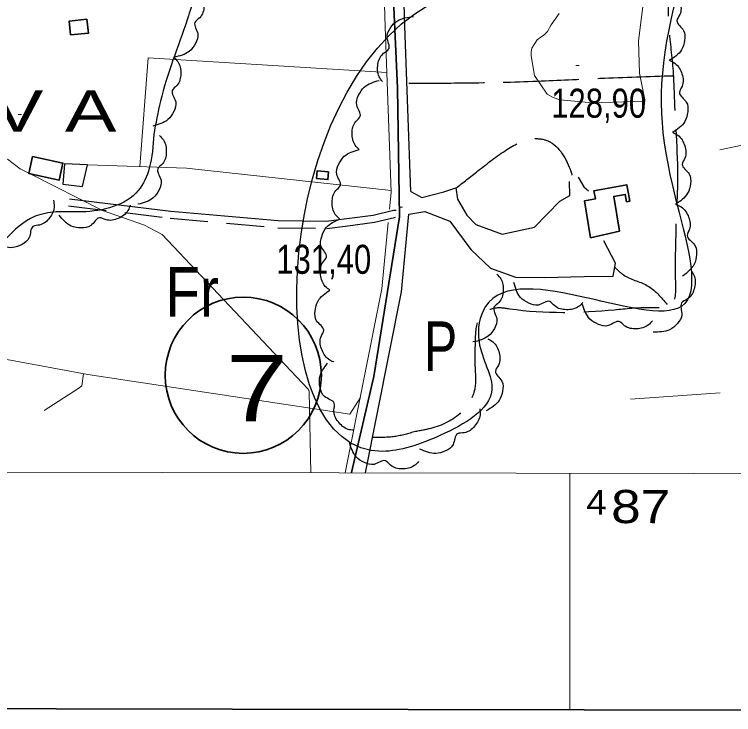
# Model space of a CAD drawing. Extents: x 483847 to 488453, y 4383581 to 4386795.
# Drawn here: x 486832.5 to 487049.4, y 4384057.5 to 4384268.7 of the extents above; entities that cross this region are included whole.
import ezdxf
from ezdxf.enums import TextEntityAlignment as Align

# ---------------------------------------------------------------- set-up
doc = ezdxf.new("R2010")
doc.units = 0
doc.header["$LTSCALE"] = 3.8
for name, pattern in [('DOTTED', [1.5, 0.3, -1.2]), ('LONG_DASHED', [7.5, 6, -1.5]), ('MEDIUM_DASHED', [4.5, 3, -1.5])]:
    doc.linetypes.add(name, pattern=pattern)
for name, color, linetype, lineweight in [('1', 7, 'Continuous', 13), ('13', 7, 'Continuous', 25), ('2', 7, 'DOTTED', 13), ('21', 7, 'Continuous', 25), ('25', 7, 'LONG_DASHED', 25), ('27', 7, 'Continuous', 25), ('38', 7, 'Continuous', 25), ('47', 7, 'Continuous', 35), ('51', 7, 'Continuous', 13), ('6', 7, 'Continuous', 35), ('7', 7, 'Continuous', 13), ('9', 7, 'Continuous', 13)]:
    doc.layers.add(name, color=color, linetype=linetype, lineweight=lineweight)
doc.layers.add('31', color=7, linetype='Continuous')
doc.layers.add('5', color=7, linetype='Continuous')

msp = doc.modelspace()

# ---------------------------------------------------------------- linework, layer by layer
at = {"layer": '1'}
msp.add_line((487000, 4384130.29), (487000, 4384058.94), dxfattribs=at)
at = {"layer": '1', "lineweight": 35}
msp.add_lwpolyline([(484035.03, 4386519.58), (487752.53, 4386512.52), (487747.86, 4384057.52), (484030.36, 4384064.59)], close=True, dxfattribs=at)
at = {"layer": '1'}
msp.add_lwpolyline([(484105.5, 4386448.1), (487681.9, 4386441.2), (487678, 4384129), (484100.5, 4384135.8)], close=True, dxfattribs=at)
at = {"layer": '21'}
msp.add_lwpolyline([(486847.61, 4384223.61), (486847.14, 4384217.46), (486852.99, 4384216.78), (486854.51, 4384223.28)], close=True, dxfattribs=at)
at = {"layer": '25'}
for points in [[(487028.81, 4384347.88), (487028.75, 4384334.02), (487028.61, 4384324.04), (487029.44, 4384308.42), (487029.78, 4384290.63), (487029.63, 4384274.58), (487029.93, 4384264.44), (487031.17, 4384251.59), (487031.57, 4384242.73), (487032.45, 4384214.81), (487032.13, 4384208.21), (487031.94, 4384200.11), (487031.85, 4384188.78), (487030.54, 4384181.07), (487024.37, 4384180.18), (487013.48, 4384179.51), (486981.9, 4384179.81), (486976.87, 4384179.96), (486972.93, 4384177.24), (486971.48, 4384170.28), (486971.44, 4384162.18), (486971.43, 4384156.1), (486967.8, 4384149.18), (486958.72, 4384143.98), (486953.45, 4384142.88)], [(487031.24, 4384250.08), (487009.08, 4384249.28), (486990.23, 4384248.43), (486968.54, 4384247.91), (486950.91, 4384247.81)], [(486953.45, 4384142.88), (486947.2, 4384141.37), (486940.49, 4384141.1)]]:
    msp.add_spline(points, degree=3, dxfattribs=at)
at = {"layer": '27'}
for points in [[(486459.96, 4384385.16), (486471.27, 4384378.47), (486473.92, 4384375.28), (486475.39, 4384367.53), (486474.06, 4384364.1), (486468.58, 4384332.36), (486456.37, 4384281.06), (486450.57, 4384253.61), (486437.24, 4384218.91), (486433.21, 4384189.18), (486433.99, 4384185.86), (486436.3, 4384184.33), (486436.97, 4384184.32), (486441.1, 4384184.71), (486447.44, 4384187.32), (486451.82, 4384188.91), (486456.5, 4384190.87), (486459.83, 4384192.92), (486472.99, 4384200.46), (486476.65, 4384203.94), (486479.61, 4384206.22), (486488.62, 4384212.32), (486496.68, 4384219.48), (486502, 4384224.06), (486511.41, 4384231.95), (486539.46, 4384262.46), (486556.14, 4384273.86), (486561.61, 4384278.73), (486564.81, 4384282.06), (486575.24, 4384313.88), (486592.54, 4384347.7), (486603.35, 4384384.68), (486618.29, 4384417.11), (486623.74, 4384425.81), (486629.81, 4384440.88), (486633.7, 4384450.43), (486641.19, 4384465.26), (486647.57, 4384470.57), (486651.57, 4384471.86), (486660.8, 4384471.88), (486687.53, 4384468.12), (486716.08, 4384460.28), (486726.32, 4384457.36), (486741.64, 4384452.94), (486747.02, 4384451.28), (486753.15, 4384449.77), (486767.51, 4384446.79), (486778.5, 4384443.85), (486779.56, 4384439.11), (486777.41, 4384419.93), (486778.13, 4384412.87), (486779.55, 4384406.62), (486783.55, 4384398.31), (486789.34, 4384388.7), (486794.95, 4384381.79), (486806.53, 4384368.27), (486812.52, 4384362.18), (486821.5, 4384354.85), (486839.86, 4384348.2), (486856.39, 4384344.37), (486864.63, 4384343.12), (486886.87, 4384340.33), (486895.94, 4384339.52), (486904.04, 4384339.11), (486909.51, 4384338.95), (486913.63, 4384337.99), (486915.08, 4384334.37), (486915.66, 4384328.28), (486915.43, 4384322.74), (486912.42, 4384321.8), (486907.78, 4384322.62), (486895.36, 4384325.35), (486888.93, 4384326.49), (486882.24, 4384325.99), (486876.01, 4384320.37), (486872.23, 4384313.15), (486873.79, 4384307.2), (486881.33, 4384304.54), (486889.2, 4384303.6), (486900.97, 4384303.06), (486911.02, 4384302.54), (486921.15, 4384302.39), (486925.48, 4384301.06), (486928.7, 4384295.53), (486929.06, 4384289.07), (486922.67, 4384283.16), (486903.92, 4384283.43), (486890.73, 4384279.42), (486884.7, 4384267.35), (486876.54, 4384242.48), (486874.52, 4384232.45)], [(486954.21, 4384387.22), (486962.95, 4384388.19), (486967.8, 4384407.6), (486993.02, 4384411.48), (487004.67, 4384398.87), (487009.52, 4384352.3), (487028.92, 4384350.36), (487029.89, 4384264), (487031.83, 4384213.55), (487034.75, 4384181.53), (486974.59, 4384180.56), (486972.65, 4384169.89), (486976.53, 4384155.33), (486961.01, 4384141.75), (486943.54, 4384136.9), (486953.24, 4384268.85), (486993.02, 4384297.96), (486990.11, 4384310.57), (486950.33, 4384311.55), (486954.21, 4384386.25)], [(486887.82, 4384276.19), (486888.96, 4384274.83), (486889.71, 4384271.11), (486888.38, 4384267.67), (486886.94, 4384266.21), (486887.81, 4384262.76), (486887.1, 4384259.86), (486885.23, 4384257.49), (486880.59, 4384255.73)], [(487029.76, 4384276.42), (487031.3, 4384275.54), (487033.27, 4384272.3), (487033.2, 4384268.61), (487032.35, 4384266.74), (487034.35, 4384263.8), (487034.68, 4384260.83), (487033.73, 4384257.96), (487029.98, 4384254.72)], [(486943.49, 4384248.4), (486942.5, 4384249.87), (486942.15, 4384253.65), (486943.84, 4384256.93), (486945.42, 4384258.24), (486944.92, 4384261.76), (486945.92, 4384264.57), (486948.04, 4384266.73), (486952.84, 4384267.98)], [(486880.56, 4384255.74), (486881.77, 4384254.43), (486882.68, 4384250.75), (486881.5, 4384247.25), (486880.13, 4384245.72), (486881.15, 4384242.32), (486880.58, 4384239.39), (486878.81, 4384236.94), (486874.25, 4384234.98)], [(487030.24, 4384254.73), (487031.8, 4384253.89), (487033.86, 4384250.7), (487033.89, 4384247.01), (487033.1, 4384245.12), (487035.18, 4384242.24), (487035.59, 4384239.28), (487034.72, 4384236.38), (487031.05, 4384233.04)], [(486936.53, 4384227.91), (486935.31, 4384229.2), (486934.35, 4384232.87), (486935.48, 4384236.38), (486936.83, 4384237.93), (486935.75, 4384241.32), (486936.29, 4384244.26), (486938.02, 4384246.73), (486942.55, 4384248.76)], [(486874.52, 4384232.45), (486873.18, 4384222.27), (486869.85, 4384215.56), (486852.95, 4384209.12), (486845.07, 4384209.09), (486838.6, 4384207.68), (486829.8, 4384200.9), (486821.86, 4384191.11), (486818.16, 4384179.23), (486817.69, 4384172.56), (486817.61, 4384162.06), (486817.76, 4384156.88), (486818.21, 4384151.39), (486817.66, 4384149.68), (486815.24, 4384148.51), (486799.94, 4384148.81), (486792.66, 4384148.98), (486785.7, 4384149.68), (486775.31, 4384158.31), (486763.92, 4384169.51), (486756.83, 4384172.53), (486747.93, 4384174.54), (486736.54, 4384175.15), (486728.96, 4384175.56), (486727.54, 4384175.65), (486725.14, 4384175.99), (486720.49, 4384175.91), (486718.03, 4384171.89), (486716.39, 4384167.41), (486710.55, 4384163.07), (486703.32, 4384161.14), (486696.72, 4384161.46), (486670.3, 4384161.09), (486638.9, 4384158.24), (486621.63, 4384157.89), (486613.98, 4384157.77), (486592.05, 4384156.66), (486586.5, 4384156.82), (486575.03, 4384157.43), (486565.06, 4384157.87), (486550.88, 4384158.23), (486543.46, 4384158.93), (486531.09, 4384160.01), (486522.17, 4384160.36), (486511.22, 4384160.44), (486505.13, 4384160.16), (486499.23, 4384156.56), (486494.51, 4384151.9), (486491.02, 4384149.03), (486481.42, 4384144.59), (486471.56, 4384142.48), (486461.81, 4384142.24), (486435.86, 4384148.54), (486429.86, 4384148.85), (486425.8, 4384148.31), (486422.94, 4384147.38), (486420.21, 4384145.62), (486415.23, 4384133.38), (486414.83, 4384131.4)], [(486876.25, 4384232.11), (486877.44, 4384230.79), (486878.32, 4384227.1), (486877.12, 4384223.61), (486875.73, 4384222.1), (486876.73, 4384218.68), (486876.13, 4384215.76), (486874.35, 4384213.32), (486869.77, 4384211.4)], [(487031.07, 4384233.04), (487032.63, 4384232.21), (487034.7, 4384229.02), (487034.73, 4384225.33), (487033.94, 4384223.44), (487036.02, 4384220.56), (487036.44, 4384217.6), (487035.57, 4384214.71), (487031.91, 4384211.36)], [(486930.52, 4384207.06), (486929.3, 4384208.35), (486928.34, 4384212.02), (486929.47, 4384215.53), (486930.82, 4384217.08), (486929.75, 4384220.47), (486930.28, 4384223.4), (486932.01, 4384225.88), (486936.54, 4384227.91)], [(486844.27, 4384212.6), (486844.49, 4384210.84), (486843.09, 4384207.31), (486840.1, 4384205.15), (486838.1, 4384204.7), (486836.95, 4384201.34), (486834.79, 4384199.29), (486831.92, 4384198.32), (486827.07, 4384199.37)], [(486867.44, 4384211.17), (486866.76, 4384209.53), (486863.8, 4384207.15), (486860.13, 4384206.74), (486858.17, 4384207.34), (486855.52, 4384204.98), (486852.62, 4384204.27), (486849.65, 4384204.84), (486845.95, 4384208.14)], [(487032.04, 4384211.37), (487033.64, 4384210.62), (487035.88, 4384207.55), (487036.12, 4384203.87), (487035.43, 4384201.94), (487037.67, 4384199.18), (487038.25, 4384196.25), (487037.54, 4384193.31), (487034.07, 4384189.76)], [(486927.67, 4384185.53), (486926.28, 4384186.64), (486924.83, 4384190.14), (486925.46, 4384193.78), (486926.59, 4384195.49), (486925.06, 4384198.7), (486925.19, 4384201.69), (486926.57, 4384204.38), (486930.77, 4384207)], [(487036.85, 4384191.19), (487037.65, 4384189.61), (487037.54, 4384185.82), (487035.47, 4384182.77), (487033.74, 4384181.65), (487033.81, 4384178.1), (487032.47, 4384175.43), (487030.12, 4384173.55), (487025.2, 4384172.88)], [(486978.06, 4384190.33), (486979.2, 4384188.96), (486979.94, 4384185.24), (486978.6, 4384181.8), (486977.16, 4384180.34), (486978.02, 4384176.89), (486977.31, 4384173.99), (486975.42, 4384171.63), (486970.78, 4384169.88)], [(487003.98, 4384181.77), (487002.68, 4384180.56), (486999.01, 4384179.61), (486995.5, 4384180.74), (486993.96, 4384182.1), (486990.56, 4384181.03), (486987.63, 4384181.58), (486985.16, 4384183.32), (486983.14, 4384187.85)], [(486928.81, 4384163.86), (486927.23, 4384164.68), (486925.12, 4384167.83), (486925.03, 4384171.52), (486925.8, 4384173.42), (486923.67, 4384176.27), (486923.21, 4384179.22), (486924.04, 4384182.13), (486927.65, 4384185.53)], [(487024.96, 4384176.29), (487023.74, 4384175.01), (487020.13, 4384173.85), (487016.56, 4384174.79), (487014.94, 4384176.06), (487011.61, 4384174.81), (487008.65, 4384175.19), (487006.09, 4384176.79), (487003.83, 4384181.2)], [(486975.35, 4384170.82), (486976.85, 4384169.89), (486978.72, 4384166.59), (486978.53, 4384162.9), (486977.62, 4384161.06), (486979.52, 4384158.06), (486979.75, 4384155.08), (486978.7, 4384152.24), (486974.83, 4384149.13)], [(486934.89, 4384143.27), (486933.14, 4384143.54), (486930.13, 4384145.86), (486928.88, 4384149.33), (486929, 4384151.38), (486926.08, 4384153.41), (486924.71, 4384156.06), (486924.57, 4384159.08), (486926.92, 4384163.45)], [(486972.85, 4384149.68), (486972.95, 4384147.9), (486971.32, 4384144.48), (486968.19, 4384142.52), (486966.16, 4384142.2), (486964.8, 4384138.92), (486962.5, 4384137.02), (486959.58, 4384136.24), (486954.81, 4384137.61)], [(486954.41, 4384133.82), (486953.12, 4384132.59), (486949.46, 4384131.62), (486945.94, 4384132.73), (486944.39, 4384134.07), (486941, 4384132.98), (486938.06, 4384133.51), (486935.58, 4384135.23), (486933.53, 4384139.75)]]:
    msp.add_spline(points, degree=3, dxfattribs=at)
at = {"layer": '38'}
for points in [[(486952.1, 4384215.22), (486950.26, 4384265.08), (486949.05, 4384305.51)], [(487002.58, 4384219.59), (487004.26, 4384216.71), (487005.67, 4384215.49)], [(486952.1, 4384215.22), (486955.44, 4384213.43), (486962.07, 4384215.14), (486965.61, 4384216.37), (486966.16, 4384212.98), (486968.95, 4384208.14), (486971.68, 4384205.32), (486979.59, 4384202.43), (486989.38, 4384204.54), (486997.07, 4384212.31), (487000.09, 4384214), (486999.93, 4384218.27)], [(486849.09, 4384213.08), (486879.71, 4384209.35), (486912.06, 4384206.49), (486926.56, 4384206.28), (486932.77, 4384207.08), (486940.72, 4384208.09), (486946.83, 4384209.58), (486947.62, 4384209.64)], [(486938.36, 4384130.41), (486949.25, 4384185.02), (486951.49, 4384208.47)], [(486951.49, 4384208.47), (486956.35, 4384209.22), (486963.82, 4384206.34), (486970.15, 4384197.77), (486976.07, 4384192.13), (486983.68, 4384189.47), (486992.39, 4384189.34), (487004.4, 4384189.62), (487013.1, 4384189.72), (487013.83, 4384193.69), (487010.33, 4384200.34)]]:
    msp.add_lwpolyline(points, dxfattribs=at)
at = {"layer": '38', "linetype": 'MEDIUM_DASHED'}
msp.add_lwpolyline([(486848.82, 4384210.95), (486879.48, 4384207.2), (486911.95, 4384204.33), (486926.69, 4384204.12), (486933.05, 4384204.95), (486941.11, 4384205.97), (486947.17, 4384207.45), (486947.41, 4384207.47)], dxfattribs=at)
at = {"layer": '38', "linetype": 'LONG_DASHED'}
for points in [[(486965.64, 4384216.21), (486972.29, 4384221.45), (486981.08, 4384227.92), (486989.38, 4384231.18), (486992.76, 4384230.76), (487000.13, 4384221.95), (487000.71, 4384220.21)], [(487013.6, 4384192.45), (487016.18, 4384190.13), (487023.27, 4384186.95), (487029.41, 4384181.16)]]:
    msp.add_spline(points, degree=3, dxfattribs=at)
at = {"layer": '47'}
for points in [[(486854.39, 4384267.18), (486854.81, 4384262.98), (486849.44, 4384262.45), (486849.02, 4384266.65)], [(486837.96, 4384225.77), (486847.14, 4384223.8), (486846.04, 4384218.68), (486836.86, 4384220.65)], [(486927.26, 4384221.19), (486927.07, 4384218.86), (486923.63, 4384219.14), (486923.82, 4384221.47)], [(487006.29, 4384201.3), (487004.42, 4384212.43), (487007.74, 4384213.03), (487007.29, 4384215.46), (487017.19, 4384217.29), (487018.1, 4384212.35), (487017.14, 4384212.18), (487016.74, 4384214.38), (487013.29, 4384213.79), (487015.07, 4384203.33)]]:
    msp.add_lwpolyline(points, close=True, dxfattribs=at)
at = {"layer": '51'}
for p, q in [((487045.24, 4384227.83), (487061.72, 4384231.2)), ((487018.35, 4384152.65), (487045.39, 4384154.52))]:
    msp.add_line(p, q, dxfattribs=at)
for points in [[(486942.92, 4384311.46), (486944.33, 4384264.88), (486946.16, 4384215.05), (486945.67, 4384209.9)], [(486944.84, 4384251.11), (486872.83, 4384255.59), (486870.32, 4384222.75)], [(486854.51, 4384223.28), (486884.43, 4384222.26), (486946.14, 4384215.52)], [(486945.29, 4384205.93), (486943.37, 4384185.89), (486932.31, 4384130.42)], [(486729.31, 4384178.71), (486802.94, 4384169.62), (486854.65, 4384160.03), (486933.64, 4384148.09), (486936.85, 4384153.15)], [(486853.3, 4384160.29), (486852.88, 4384156.68), (486851.66, 4384155.79), (486841.44, 4384149.19)]]:
    msp.add_lwpolyline(points, dxfattribs=at)
at = {"layer": '6'}
msp.add_lwpolyline([(486934.14, 4384130.55), (486940.93, 4384159.51), (486948.64, 4384207.59), (486948.03, 4384246.42), (486946.18, 4384288.58), (486945.56, 4384310.48)], dxfattribs=at)
msp.add_circle((486901.53, 4384159.85), 23.55, dxfattribs=at)
at = {"layer": '7'}
for p, q in [((487001.88, 4384253.28), (487002.88, 4384253.28)), ((486833.66, 4384238.51), (486834.66, 4384238.51)), ((486948.52, 4384210.52), (486949.52, 4384210.52))]:
    msp.add_line(p, q, dxfattribs=at)
at = {"layer": '9'}
for points in [[(487024.47, 4384290.15), (487020.8, 4384260.7), (487021.08, 4384250.91), (487022.68, 4384242.91), (487022.64, 4384242.82), (487022.62, 4384242.74), (487022.62, 4384242.53), (487022.58, 4384242.39), (487022.54, 4384242.39), (487022.5, 4384242.39), (487022.26, 4384242.54), (487006.87, 4384242.01), (486997.04, 4384242.86), (486995, 4384243.63), (486993.25, 4384244.63), (486989.41, 4384250.19), (486988.36, 4384256.15), (486988.38, 4384257.41), (486988.53, 4384258.5), (486990.21, 4384261.03), (486992.41, 4384262.58), (486993.31, 4384263.55), (486994.38, 4384265.47), (486996.87, 4384268.95)], [(486836.88, 4384220.75), (486834.2, 4384222.11), (486830.43, 4384224.98)], [(486921.87, 4384130.44), (486921.37, 4384154.99), (486921.34, 4384155.22), (486921.27, 4384155.38), (486921.05, 4384155.72), (486877.08, 4384202.29), (486871.77, 4384205.14), (486859.11, 4384209.49), (486837.24, 4384220.57)]]:
    msp.add_lwpolyline(points, dxfattribs=at)

# ---------------------------------------------------------------- texts
at = {"layer": '13', "width": 1.25}
msp.add_text('7', height=20, dxfattribs=at).set_placement((486905.66, 4384145.97), align=Align.CENTER)
at = {"layer": '2'}
for s, height, width, p in [('4', 7.5, 1.1, (487004.99, 4384117.78)), ('87  ', 10, 1.2, (487012.48, 4384115.27))]:
    msp.add_text(s, height=height, rotation=359.891, dxfattribs=dict(at, width=width)).set_placement(p)
at = {"layer": '31'}
for s, width, p in [('Fr', 0.85, (486886.1, 4384177.49)), ('P', 0.75, (486961.07, 4384161.08))]:
    msp.add_text(s, height=15, dxfattribs=dict(at, width=width)).set_placement(p, align=Align.CENTER)
at = {"layer": '5', "width": 1.4}
msp.add_text('C A N   F A V A', height=12.49, dxfattribs=at).set_placement((486700.89, 4384233.25))
at = {"layer": '7', "width": 0.8}
for s, p in [('128,90', (486994.42, 4384237.51)), ('131,40', (486911.5, 4384190.43))]:
    msp.add_text(s, height=8.75, dxfattribs=at).set_placement(p)

doc.saveas('drawing.dxf')
